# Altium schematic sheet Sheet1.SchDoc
size A4; SheetNumber: 1; SheetTotal: 1
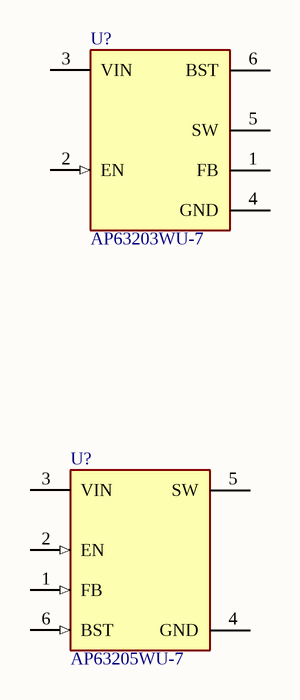
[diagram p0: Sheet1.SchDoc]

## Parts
(Parts that share a designator on the sheet are numbered #1, #2 ... from top to bottom, then left to right.)
U?#1  AP63203WU-7  [FP-TSOT26-MFG]
U?#2  AP63205WU-7  [FP-TSOT26-MFG]

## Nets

Not connected (* = marked no-connect by the designer): U?#1 1(FB) 2(EN) 3(VIN) 4(GND) 5(SW) 6(BST); U?#2 1(FB) 2(EN) 3(VIN) 4(GND) 5(SW) 6(BST)

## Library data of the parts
U?#1 = CMP-12757-000006-1: IC REG BUCK 3.3V 2A TSOT26; Manufacturer: Diodes Inc.; Description: Buck Switching Regulator IC Positive Fixed 3.3V 1 Output 2A SOT-23-6 Thin, TSOT-23-6; Output Type: Fixed; Min Supply Voltage: 3.8V; Number Of Outputs: 1; Max Junction Temp: +160°C; Nominal Supply Current: 22uA; Standoff Height: 0.01mm; Switching Frequency: 1.1MHz; Max Supply Voltage: 32V
U?#2 = CMP-12757-000001-1: IC REG BUCK 5V 2A TSOT26; Manufacturer: Diodes Inc.; Max Junction Temp: +160°C; Max Duty Cycle: 100%; Standoff Height: 0.01mm; Max Supply Voltage: 32V; Number Of Outputs: 1; Description: Buck Switching Regulator IC Positive Fixed 5V 1 Output 2A SOT-23-6 Thin, TSOT-23-6; Min Supply Voltage: 3.8V; Output Type: Fixed; Switching Frequency: 1100kHz; Nominal Supply Current: 22uA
